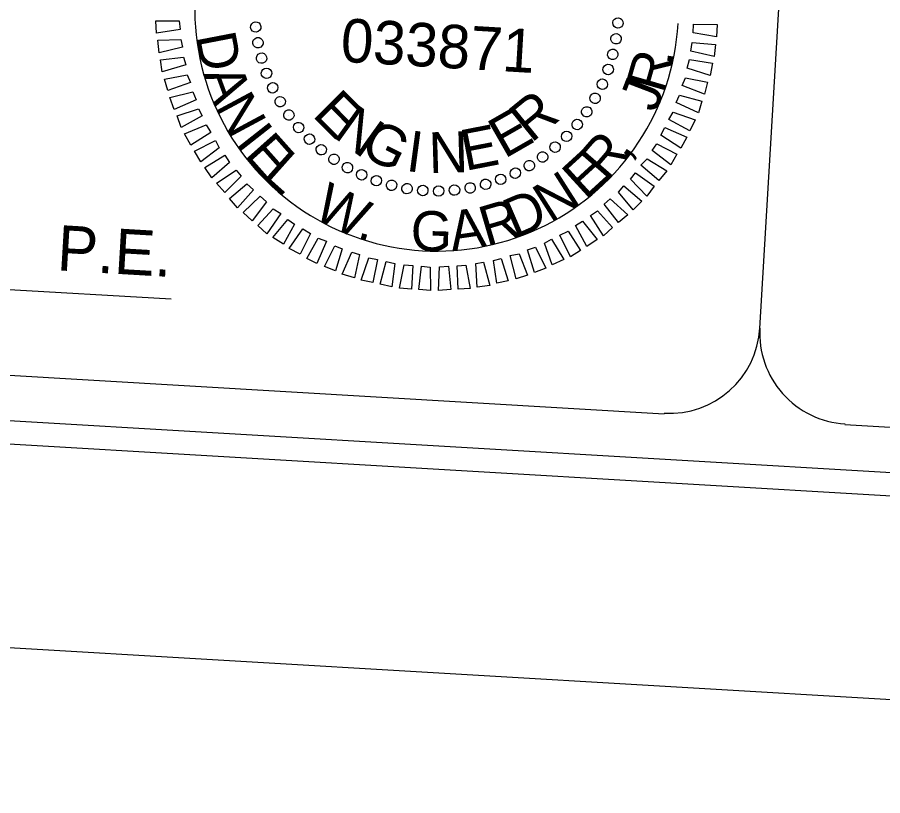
# Model space of a CAD drawing. Extents: x 1998567 to 2027801, y 439108 to 451079.
# Drawn here: x 2017808 to 2018763, y 439108 to 439966 of the extents above; entities that cross this region are included whole.
import ezdxf

# ---------------------------------------------------------------- set-up
doc = ezdxf.new("R2010")
doc.units = 0
for name, color, linetype in [('Scratch_Level_0', 7, 'Continuous'), ('Sheet Cutting Line CELL', 7, 'Continuous'), ('Sheet Plot Border Inside CELL', 7, 'Continuous'), ('Sheet Plot Border Outside CELL', 7, 'Continuous'), ('Sheet Professional Seal CELL', 7, 'Continuous'), ('Sheet Profile Grid Minor CELL', 7, 'Continuous'), ('Sheet Title CELL', 7, 'Continuous')]:
    doc.layers.add(name, color=color, linetype=linetype)

msp = doc.modelspace()

# ---------------------------------------------------------------- linework, layer by layer
at = {"layer": 'Scratch_Level_0'}
msp.add_arc((2018271.09, 439975.33), 266.91, 176.62643, 356.62643, dxfattribs=at)
at = {"layer": 'Sheet Cutting Line CELL'}
msp.add_line((2003762.2, 440098.56), (2020573.02, 439107.6), dxfattribs=at)
at = {"layer": 'Sheet Plot Border Inside CELL'}
msp.add_lwpolyline([(2003905.18, 440314.9), (2020541.3, 439334.23), (2021162.18, 449866.95), (2004526.06, 450847.62)], close=True, dxfattribs=at)
at = {"layer": 'Sheet Plot Border Outside CELL'}
msp.add_lwpolyline([(2021220.31, 450088.41), (2004409.5, 451079.38), (2003762.2, 440098.56), (2020573.02, 439107.6)], close=True, dxfattribs=at)
at = {"layer": 'Sheet Professional Seal CELL'}
for p, q in [((2018071.6, 439955.83), (2018071.6, 439955.83)), ((2018471.33, 439959.92), (2018471.33, 439959.92)), ((2018469.1, 439942.42), (2018469.1, 439942.42)), ((2018073.76, 439938.08), (2018073.76, 439938.08)), ((2018465.29, 439925.41), (2018465.29, 439925.41)), ((2018077.56, 439921.02), (2018077.56, 439921.02)), ((2018083.01, 439904.67), (2018083.01, 439904.67)), ((2018460.71, 439908.86), (2018460.71, 439908.86)), ((2018090.07, 439888.63), (2018090.07, 439888.63)), ((2018454.13, 439892.41), (2018454.13, 439892.41)), ((2018446, 439876.87), (2018446, 439876.87)), ((2018098.36, 439872.92), (2018098.36, 439872.92)), ((2018107.52, 439858.35), (2018107.52, 439858.35)), ((2018437.09, 439861.76), (2018437.09, 439861.76)), ((2018426.26, 439847.98), (2018426.26, 439847.98)), ((2018118.73, 439844.47), (2018118.73, 439844.47)), ((2018130.4, 439831.76), (2018130.4, 439831.76)), ((2018414.66, 439834.64), (2018414.66, 439834.64)), ((2018143.74, 439820.15), (2018143.74, 439820.15)), ((2018401.95, 439822.96), (2018401.95, 439822.96)), ((2018157.52, 439809.32), (2018157.52, 439809.32)), ((2018388.07, 439811.76), (2018388.07, 439811.76)), ((2018172.63, 439800.42), (2018172.63, 439800.42)), ((2018373.5, 439802.6), (2018373.5, 439802.6)), ((2018188.18, 439792.29), (2018188.18, 439792.29)), ((2018357.79, 439794.31), (2018357.79, 439794.31)), ((2018204.62, 439785.71), (2018204.62, 439785.71)), ((2018221.18, 439781.13), (2018221.18, 439781.13)), ((2018325.4, 439781.8), (2018325.4, 439781.8)), ((2018341.74, 439787.25), (2018341.74, 439787.25)), ((2018238.18, 439777.32), (2018238.18, 439777.32)), ((2018255.68, 439775.09), (2018255.68, 439775.09)), ((2018273.27, 439774.45), (2018273.27, 439774.45)), ((2018290.58, 439775.84), (2018290.58, 439775.84)), ((2018308.34, 439778), (2018308.34, 439778))]:
    msp.add_line(p, q, dxfattribs=at)
for points in [[(2017988.07, 439952.74), (2017961.79, 439948.68), (2017961.39, 439962.33), (2017987.04, 439962.42)], [(2018554.6, 439958.62), (2018580.62, 439958.28), (2018579.82, 439944.71), (2018554.03, 439949.03)], [(2017990.53, 439933.37), (2017964.93, 439927.26), (2017963.34, 439940.98), (2017988.63, 439941.89)], [(2018553.02, 439938.68), (2018578.93, 439936.35), (2018577.35, 439923.22), (2018551.66, 439929.14)], [(2017994.2, 439913.92), (2017968.1, 439906.24), (2017966.48, 439919.56), (2017991.9, 439922.47)], [(2018549.9, 439919.63), (2018575.31, 439915.72), (2018572.91, 439902.24), (2018547.33, 439910.16)], [(2017999.46, 439894.37), (2017974.49, 439885.43), (2017970.82, 439898.06), (2017995.96, 439902.99)], [(2018545.5, 439899.45), (2018570.07, 439894.8), (2018566.47, 439881.38), (2018541.81, 439891.25)], [(2018005.54, 439875.18), (2017981.27, 439864.59), (2017976.83, 439877.68), (2018002.06, 439884.2)], [(2018539.18, 439880.59), (2018563.63, 439873.94), (2018560.06, 439860.93), (2018535.49, 439872.39)], [(2018012.51, 439857.54), (2017989.33, 439844.88), (2017984.86, 439857.57), (2018008.17, 439865.41)], [(2018532.06, 439861.78), (2018556.39, 439853.13), (2018550.47, 439841.06), (2018527.17, 439853.65)], [(2018021.86, 439839.36), (2017999.8, 439825.43), (2017992.92, 439837.86), (2018016.74, 439847.68)], [(2018523.04, 439844.68), (2018547.25, 439834.03), (2018540.53, 439822.01), (2018518.53, 439836.13)], [(2018031.27, 439822.38), (2018010.72, 439806.76), (2018003.81, 439818.79), (2018026.93, 439830.25)], [(2018513.97, 439826.78), (2018536.14, 439815.45), (2018529.42, 439803.43), (2018508.73, 439819.47)], [(2018042.33, 439806.1), (2018022.91, 439789.21), (2018015.16, 439800.49), (2018037.22, 439814.41)], [(2018503.37, 439810.17), (2018525.03, 439796.88), (2018516.38, 439786.17), (2018496.56, 439803.36)], [(2018055.46, 439790.9), (2018037.19, 439773.14), (2018028.17, 439783.29), (2018049.85, 439797.64)], [(2018490.45, 439794.91), (2018511.22, 439780.06), (2018502.95, 439768.93), (2018484.81, 439787.63)], [(2018069.01, 439776.08), (2018051.42, 439756.28), (2018042.4, 439766.42), (2018061.78, 439782.51)], [(2018477.58, 439780.44), (2018497.43, 439763.64), (2018488.03, 439753.78), (2018471.57, 439773.58)], [(2018083.46, 439762.8), (2018067.39, 439741.71), (2018057.53, 439751.11), (2018076.2, 439768.84)], [(2018462.71, 439766.09), (2018482.11, 439748.52), (2018471.58, 439739.92), (2018455.94, 439760.08)], [(2018099.12, 439749.86), (2018083.78, 439727.52), (2018073.9, 439736.52), (2018090.62, 439755.17)], [(2018448.71, 439752.89), (2018465.24, 439734.29), (2018455.09, 439725.27), (2018440.79, 439747.75)], [(2018114.06, 439738.16), (2018101.94, 439716.03), (2018090.36, 439723.53), (2018106.76, 439743.4)], [(2018432.01, 439741.45), (2018448.05, 439721.28), (2018436.77, 439713.53), (2018424.11, 439736.71)], [(2018131.89, 439727.89), (2018120.52, 439704.92), (2018108.47, 439711.24), (2018123.36, 439732.8)], [(2018149.41, 439719.25), (2018138.74, 439694.63), (2018127.84, 439700.08), (2018140.39, 439722.58)], [(2018397.97, 439721.42), (2018411.47, 439698.99), (2018398.72, 439693.33), (2018390.1, 439717.08)], [(2018416.13, 439730.37), (2018429.7, 439709.13), (2018418.87, 439702.16), (2018407.06, 439726.1)], [(2018166.95, 439711), (2018159.51, 439686.6), (2018147.36, 439691.32), (2018158.73, 439714.29)], [(2018380.23, 439712.85), (2018391.69, 439689.74), (2018378.98, 439684.88), (2018371.24, 439709.78)], [(2018185.82, 439704.68), (2018180.29, 439678.96), (2018166.9, 439682.95), (2018177.55, 439707.17)], [(2018362.17, 439705.5), (2018371.19, 439681.73), (2018358.92, 439677.64), (2018352.05, 439703.69)], [(2018205.92, 439699.09), (2018200.82, 439673.74), (2018187.76, 439676.51), (2018196.41, 439700.85)], [(2018224.9, 439694.76), (2018221.77, 439668.9), (2018208.74, 439672.07), (2018215.41, 439696.92)], [(2018244.79, 439692.39), (2018243.26, 439666.43), (2018230.11, 439667.61), (2018235.23, 439693.35)], [(2018303.33, 439692.94), (2018308.21, 439667.01), (2018294.96, 439666.59), (2018293.67, 439692.31)], [(2018322.75, 439696.21), (2018329.66, 439670.55), (2018315.92, 439668.56), (2018314.25, 439694.7)], [(2018342.23, 439700.27), (2018350, 439675.77), (2018337.41, 439672.9), (2018333.68, 439697.97)], [(2018263.94, 439690.86), (2018264.4, 439664.78), (2018251.25, 439665.96), (2018254.38, 439691.82)], [(2018284.02, 439691.68), (2018286.91, 439665.86), (2018273.24, 439665.07), (2018274.37, 439691.04)]]:
    msp.add_lwpolyline(points, close=True, dxfattribs=at)
for centre, major_axis in [((2018071.42, 439955.66), (-5.73, -0.56)), ((2018471.15, 439960.03), (5.74, -0.44)), ((2018073.89, 439938.33), (-5.66, -1.06)), ((2018469.05, 439942.65), (5.68, -0.94)), ((2018465.45, 439925.52), (5.58, -1.43)), ((2018077.87, 439921.28), (-5.55, -1.55)), ((2018460.37, 439908.77), (5.43, -1.91)), ((2018083.31, 439904.65), (-5.39, -2.03)), ((2018090.19, 439888.55), (-5.19, -2.49)), ((2018453.85, 439892.53), (5.25, -2.38)), ((2018098.44, 439873.12), (-4.96, -2.93)), ((2018445.94, 439876.91), (5.02, -2.83)), ((2018108, 439858.46), (-4.68, -3.36)), ((2018436.69, 439862.05), (4.75, -3.25)), ((2018118.81, 439844.69), (-4.37, -3.75)), ((2018426.19, 439848.05), (4.45, -3.65)), ((2018130.78, 439831.91), (-4.03, -4.12)), ((2018414.51, 439835.01), (4.12, -4.03)), ((2018143.81, 439820.23), (-3.65, -4.45)), ((2018401.73, 439823.05), (3.75, -4.37)), ((2018387.96, 439812.24), (3.36, -4.68)), ((2018157.81, 439809.73), (-3.25, -4.75)), ((2018373.3, 439802.68), (2.93, -4.96)), ((2018172.68, 439800.48), (-2.83, -5.02)), ((2018188.29, 439792.57), (-2.38, -5.25)), ((2018357.87, 439794.43), (2.49, -5.19)), ((2018204.53, 439786.05), (-1.91, -5.43)), ((2018325.14, 439782.11), (1.55, -5.55)), ((2018341.77, 439787.55), (2.03, -5.39)), ((2018221.28, 439780.97), (-1.43, -5.58)), ((2018238.41, 439777.37), (-0.94, -5.68)), ((2018255.79, 439775.27), (-0.44, -5.74)), ((2018273.28, 439774.7), (0.06, -5.76)), ((2018290.76, 439775.66), (0.56, -5.73)), ((2018308.09, 439778.13), (1.06, -5.66))]:
    msp.add_ellipse(centre, major_axis=major_axis, ratio=0.999708, dxfattribs=at)
at = {"layer": 'Sheet Title CELL'}
for p, q in [((2018627.68, 439622.97), (2018721.83, 441220.19)), ((2016565.73, 439739), (2017978.27, 439655.61))]:
    msp.add_line(p, q, dxfattribs=at)
for points in [[(2005543.83, 440243.85), (2020318.19, 439372.93)], [(2016527.72, 439646.58), (2018522.01, 439529.02)], [(2018721.66, 439517.25), (2020271.22, 439425.91)]]:
    msp.add_lwpolyline(points, dxfattribs=at)
for centre, start, end in [((2018527.93, 439629.42), 266.62643, 356.62643), ((2018727.58, 439617.65), 176.62643, 266.62643)]:
    msp.add_arc(centre, 100, start, end, dxfattribs=at)

# ---------------------------------------------------------------- texts
at = {"layer": 'Sheet Professional Seal CELL'}
for s, height, rotation, p in [('E', 45.1, 314.90331, (2018132.75, 439858.07)), ('R', 45.11, 39.10783, (2018375.34, 439826.94)), ('N', 45.11, 324.26038, (2018155.44, 439835.09)), ('E', 45.11, 29.75051, (2018345.88, 439809.84)), ('G', 45.11, 333.61666, (2018184.73, 439815.33)), ('E', 45.11, 11.03819, (2018302.64, 439796.76)), ('I', 45.1, 352.32763, (2018236.14, 439797.08)), ('N', 45.1, 1.68281, (2018262.82, 439794.3))]:
    msp.add_text(s, height=height, rotation=rotation, dxfattribs=at).set_placement(p)
at = {"layer": 'Sheet Profile Grid Minor CELL'}
for s, height, rotation, p in [('033871', 47.986, 356.62643, (2018164.31, 439917.45)), ('D', 44, 280.89464, (2018004.96, 439945.8)), ('R', 44, 73.98048, (2018521.76, 439881.2)), ('.', 44, 80.90693, (2018531.28, 439912.11)), ('A', 44, 290.03926, (2018013.04, 439903.88)), ('J', 44, 69.11194, (2018512.86, 439860.26)), ('N', 44, 298.22506, (2018025.84, 439867.86)), ('I', 44, 308.15678, (2018048.05, 439827.18)), ('E', 44, 311.67724, (2018057.57, 439813.76)), ('R', 44, 49.00522, (2018458.57, 439784.16)), ('L', 44, 318.26022, (2018077.5, 439790.35)), ('E', 44, 42.42223, (2018435.42, 439763.93)), (',', 44, 55.93166, (2018480.26, 439808.17)), ('N', 44, 32.49052, (2018396.5, 439738.75)), ('W', 44, 333.51557, (2018133, 439745.93)), ('D', 44, 23.34589, (2018357.31, 439721.83)), ('R', 44, 16.41945, (2018326.11, 439713.28)), ('G', 44, 358.30194, (2018241.89, 439709.17)), ('A', 44, 8.23365, (2018288.23, 439708.12)), ('.', 44, 345.12166, (2018181.97, 439722.84))]:
    msp.add_text(s, height=height, rotation=rotation, dxfattribs=at).set_placement(p)
at = {"layer": 'Sheet Title CELL'}
msp.add_text('P.E.', height=49.995, rotation=356.62643, dxfattribs=at).set_placement((2017851.41, 439687.26))

doc.saveas('drawing.dxf')
